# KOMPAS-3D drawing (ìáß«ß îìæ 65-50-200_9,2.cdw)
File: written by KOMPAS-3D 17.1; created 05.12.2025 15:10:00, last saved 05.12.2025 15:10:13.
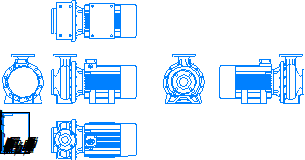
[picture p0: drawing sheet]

Sheet 1: A4, portrait

Title block, sheet 1: name: Насос МНС / 65-50-200_9,2; material: Сталь 10  ГОСТ 1050-88; mass: 183,14; sheets: 1; sheet format: A4

Views: Вид 1, Спереди, Проекционный вид 2, Проекционный вид 3, Проекционный вид 4, Проекционный вид 6
Referenced files in \\adlc.lan\data\АДЛ_ПКД\3D-модели\ADL production\Насосы ГРАНПАМП\Насосы ГРАНПАМП серии МНС\KOMPAS 3D\: Насос МНС 65-50-200_9,2.m3d
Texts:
  Andrey
  АДЛ
Dimensions and other numbers on the sheet: 1:1; 1; 65-50-200_9,2; 183,14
